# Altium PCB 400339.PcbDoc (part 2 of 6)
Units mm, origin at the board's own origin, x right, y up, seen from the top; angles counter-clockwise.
Board outline 146 x 63.5 mm, 4 copper layers (Top Layer, Mid-Layer 1, Mid-Layer 2, Bottom Layer), stack 1.505 mm thick; 400 components, 261 nets, 1523 pads, 1938 vias.
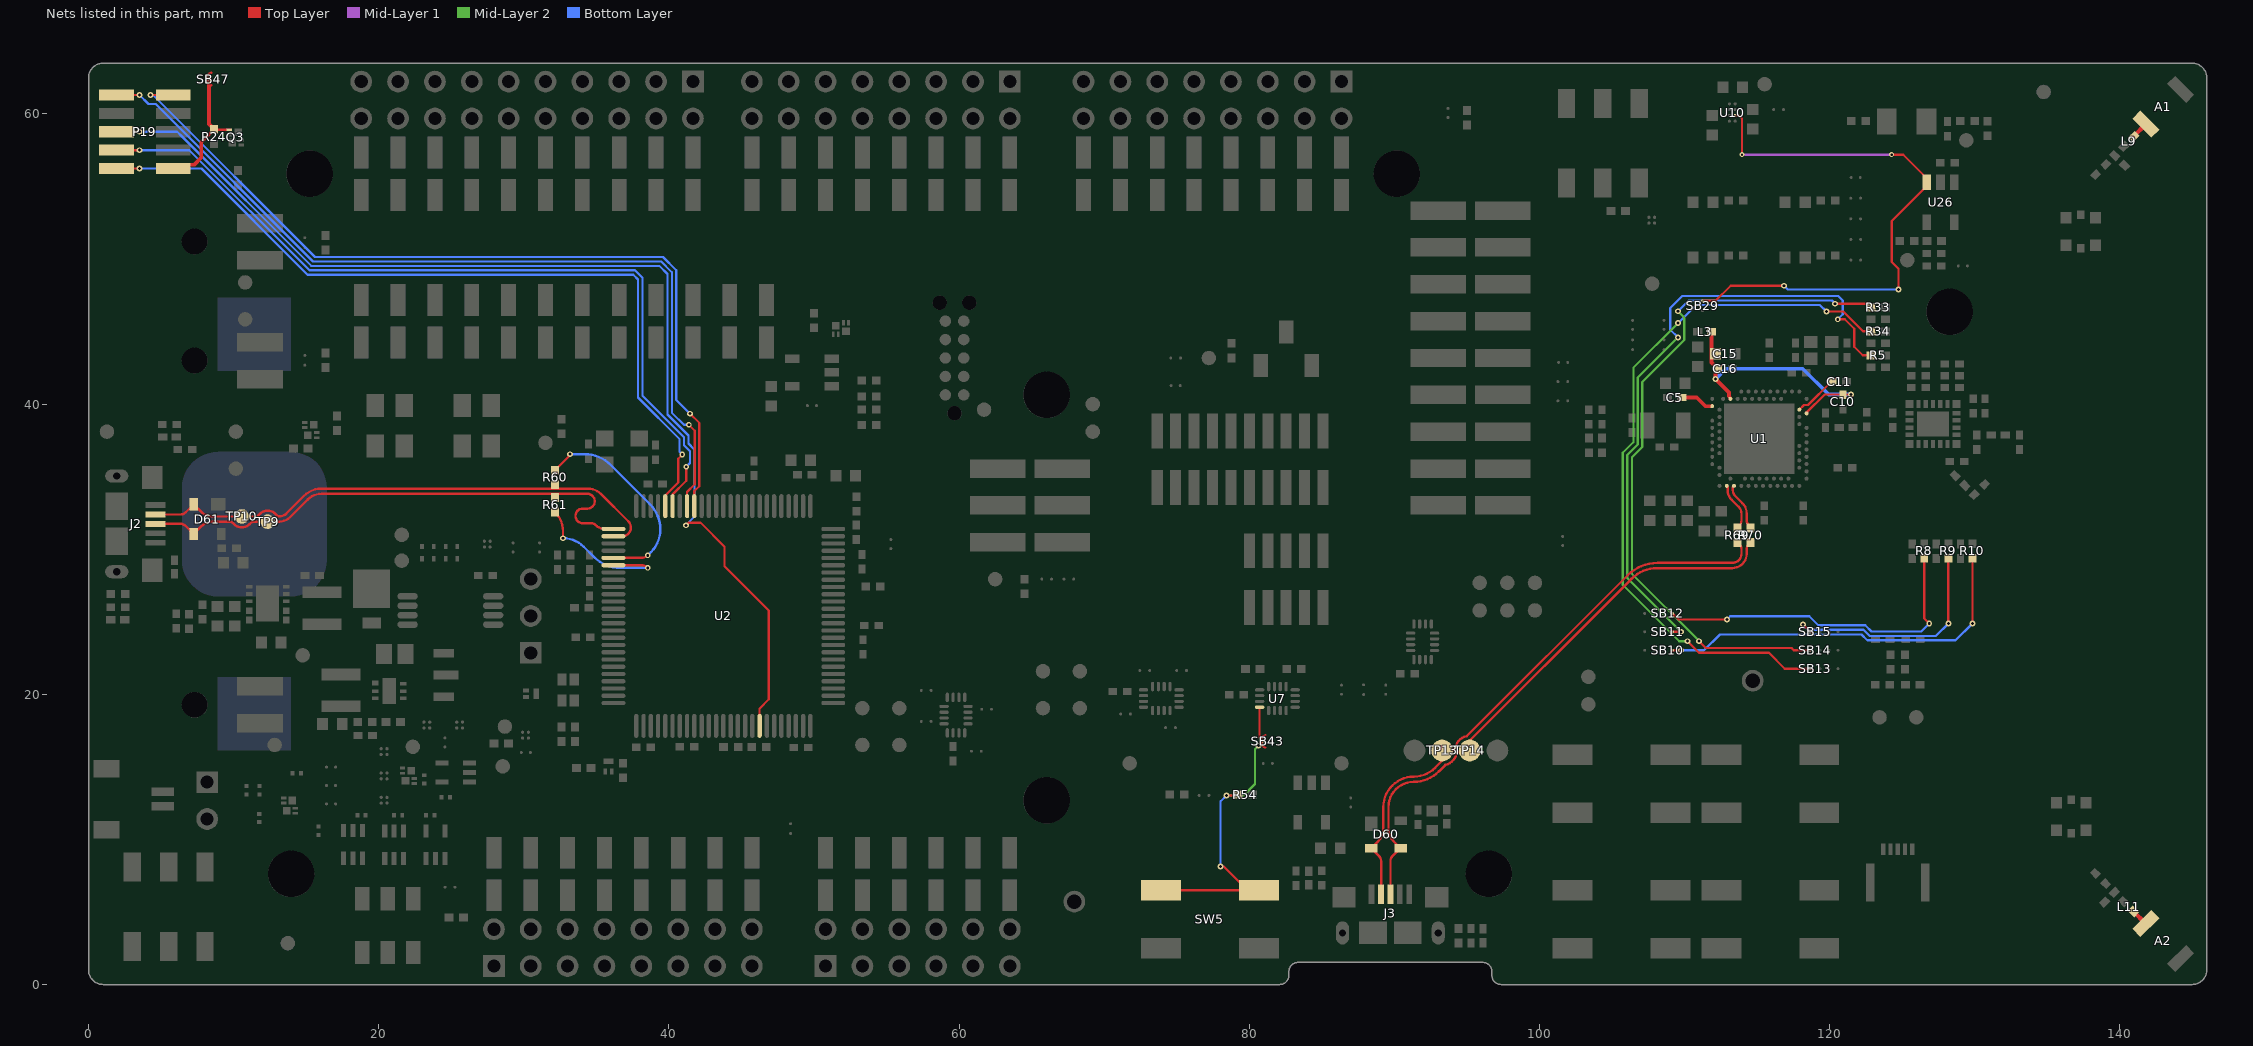
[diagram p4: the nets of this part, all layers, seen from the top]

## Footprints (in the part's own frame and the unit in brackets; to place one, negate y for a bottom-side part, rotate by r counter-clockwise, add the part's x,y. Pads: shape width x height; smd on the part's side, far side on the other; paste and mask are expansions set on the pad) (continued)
Solderbridge#4 [mm]
  round 0.2 smd paste-10: 1(-0.312,0) 2(0.312,0)
  Top Layer region: -0.077,-0.432 -0.152,-0.505 -0.271,-0.467 -0.335,-0.424 -0.409,-0.351 -0.462,-0.292 -0.521,-0.193 -0.549,-0.099 -0.544,0.122 -0.518,0.193 -0.434,0.33 -0.351,0.411 -0.259,0.469 -0.157,0.5 -0.107,0.483 -0.077,0.43
  Top Layer region: 0.077,0.432 0.152,0.505 0.271,0.467 0.335,0.424 0.409,0.351 0.462,0.292 0.521,0.193 0.549,0.099 0.544,-0.122 0.518,-0.193 0.434,-0.33 0.351,-0.411 0.259,-0.469 0.157,-0.5 0.107,-0.483 0.077,-0.43
  Top Layer lines w0.152: 0.153,0.431 cw(c0.042,0) 0.487,0 cw(c0.042,0) 0.312,-0.353 cw(c0.042,0) 0.153,-0.431 ; -0.153,0.431 ccw(c-0.042,0) -0.487,0 ccw(c-0.042,0) -0.153,-0.431
Solderbridge#5 [mm]
  round 0.2 smd paste-10: 1(-0.312,0) 2(0.312,0)
  Top Layer region: -0.077,-0.432 -0.152,-0.505 -0.271,-0.467 -0.335,-0.424 -0.409,-0.351 -0.462,-0.292 -0.521,-0.193 -0.549,-0.099 -0.544,0.122 -0.518,0.193 -0.434,0.33 -0.351,0.411 -0.259,0.469 -0.157,0.5 -0.107,0.483 -0.077,0.43
  Top Layer region: 0.077,0.432 0.152,0.505 0.271,0.467 0.335,0.424 0.409,0.351 0.462,0.292 0.521,0.193 0.549,0.099 0.544,-0.122 0.518,-0.193 0.434,-0.33 0.351,-0.411 0.259,-0.469 0.157,-0.5 0.107,-0.483 0.077,-0.43
  Top Layer lines w0.152: 0.153,0.431 cw(c0.042,0) 0.487,0 cw(c0.042,0) 0.153,-0.431 ; -0.153,0.431 ccw(c-0.042,0) -0.315,0.351 ccw(c-0.042,0) -0.482,0.066 ccw(c-0.042,0) -0.315,-0.351 ccw(c-0.042,0) -0.153,-0.431
Solderbridge_Shorted#1 [mm]
  round 0.2 smd paste-10: 1(-0.338,0) 2(0.338,0)
  Top Layer region: 0.102,0.432 0.178,0.505 0.296,0.467 0.361,0.424 0.434,0.351 0.488,0.292 0.546,0.193 0.574,0.099 0.569,-0.122 0.544,-0.193 0.46,-0.33 0.376,-0.411 0.284,-0.469 0.183,-0.5 0.132,-0.483 0.102,-0.43
  Top Layer region: -0.102,-0.432 -0.178,-0.505 -0.296,-0.467 -0.361,-0.424 -0.434,-0.351 -0.488,-0.292 -0.546,-0.193 -0.574,-0.099 -0.569,0.122 -0.544,0.193 -0.46,0.33 -0.376,0.411 -0.284,0.469 -0.183,0.5 -0.132,0.483 -0.102,0.43
  Top Layer lines w0.152: -0.178,0.431 ccw(c-0.068,0) -0.178,-0.431 ; 0.178,0.431 cw(c0.068,0) 0.178,-0.431
  Top Layer lines w0.203: -0.338,0 0.338,0
Solderbridge_Shorted#2 [mm]
  round 0.2 smd paste-10: 1(-0.338,0) 2(0.338,0)
  Top Layer region: 0.102,0.432 0.178,0.505 0.296,0.467 0.361,0.424 0.434,0.351 0.488,0.292 0.546,0.193 0.574,0.099 0.569,-0.122 0.544,-0.193 0.46,-0.33 0.376,-0.411 0.284,-0.469 0.183,-0.5 0.132,-0.483 0.102,-0.43
  Top Layer region: -0.102,-0.432 -0.178,-0.505 -0.296,-0.467 -0.361,-0.424 -0.434,-0.351 -0.488,-0.292 -0.546,-0.193 -0.574,-0.099 -0.569,0.122 -0.544,0.193 -0.46,0.33 -0.376,0.411 -0.284,0.469 -0.183,0.5 -0.132,0.483 -0.102,0.43
  Top Layer lines w0.152: -0.178,-0.431 cw(c-0.068,0) -0.512,0 cw(c-0.068,0) -0.178,0.431 ; 0.178,-0.431 ccw(c0.068,0) 0.178,0.431
  Top Layer lines w0.203: -0.338,0 0.338,0
SOT65P210X100-5N [mm] "SOT23, 5-Leads, Body 2,2x2,4mm (max), Pitch 0,65mm, IPC Medium Density"
  rect 0.9x0.35 smd: 1(-0.95,0.65) 2(-0.95,0) 3(-0.95,-0.65) 4(0.95,-0.65) 5(0.95,0.65)
  silkscreen extent -1.08,-1.1 0.1,1.5, body extent -1.1,-1 1.1,1, height 0.97
SOT65P210X100-6N [mm] "SOT23, 6-Leads, Body 2,2x2,4mm (max), Pitch 0,65mm, IPC Medium Density"
  rect 0.9x0.35 smd: 1(-0.95,0.65) 2(-0.95,0) 3(-0.95,-0.65) 4(0.95,-0.65) 5(0.95,0) 6(0.95,0.65)
  silkscreen extent -1.41,-1.1 0.1,1.34, body extent -1.05,-1 1.05,1, height 0.92
SOT89-150P409X160-3N [mm] "SOT89, 3-Leads, Body 4.50x2.45mm, Pitch 1.50mm, Lead Span 4.1mm, IPC Medium Density"
  rect 1.4x0.6 smd: 1(-1.8,1.5) 3(-1.8,-1.5)
  rect 1.7x0.6 smd: 2(-1.65,0)
  Top Layer region: -0.8,0.3 -0.15,0.95 1.85,0.95 2.5,0.3 2.5,-0.3 1.85,-0.95 -0.15,-0.95 -0.8,-0.3
  silkscreen extent -2.05,-2.3 1.32,2.47, body extent -2.2,-2.3 1.93,2.3, height 1.6
SOT95P280X140-5N [mm] "SOT23, 5-Leads, Body 2,90x2,80mm, Pitch 0,95mm, IPC Medium Density"
  rect 1x0.6 smd: 1(-1.35,0.95) 2(-1.35,0) 3(-1.35,-0.95) 4(1.35,-0.95) 5(1.35,0.95)
  silkscreen extent -1.47,-1.5 0.45,1.93, body extent -1.5,-1.55 1.5,1.55, height 1.4
SOT95P282X145-5N [mm] "SOT23, 5-Leads, Body 2.96x2.82mm, Pitch 0.95mm, IPC Medium Density"
  rect 1.05x0.6 smd: 1(-1.375,0.95) 2(-1.375,0) 3(-1.375,-0.95) 4(1.375,-0.95) 5(1.375,0.95)
  silkscreen extent -1.5,-1.55 0.45,1.93, body extent -1.5,-1.55 1.5,1.55, height 1.45
SOT190P230X110-4L [mm] "SOT143, 4-Leads, Body 3.0x2.5mm (max), Pitch 1.90mm, IPC High Density"
  rect 0.85x1 smd: 1(-1.025,0.75)
  rect 0.85x0.6 smd: 2(-1.025,-0.95) 3(1.025,-0.95) 4(1.025,0.95)
  silkscreen extent -1.15,-1.5 0.7,1.92, body extent -1.21,-1.46 1.21,1.46, height 1
Switch-PB-6.2x6.3mm-SMD [mm] "6.2×6.5mm TACT Switch, without ground connector"
  rect 2.75x1.4 smd: 1(-3.375,2) 1(3.375,2) 2(-3.375,-2) 2(3.375,-2)
  silkscreen extent -3,-3 3,3, body extent -4,-3 4,3.3, height 3.1
Switch-Slide-J-Lead-DP3T-13x3.5mm [mm] "Slide Switch - DP3T, SMD, ON-ON-ON"
  rect 1.2x1.6 smd: 1(-4,-1.4) 2(-2,-1.4) 3(2,-1.4) 4(4,-1.4) 5(-4,1.4) 6(-2,1.4) 7(2,1.4) 8(4,1.4)
  silkscreen extent -6,-1.75 6,1.75, body extent -6,-1.8 6,1.7, height 5.5
TC2050-IDC-NLFP [mil]
  round 39 hole 39 unplated: 0(-150,0) 0(150,-40) 0(150,40)
  round 31 smd paste-196.85: 1(-100,-25) 2(-50,-25) 3(0,-25) 4(50,-25) 5(100,-25) 6(100,25) 7(50,25) 8(0,25) 9(-50,25) 10(-100,25)
  Top Layer pour cut-out: -100,25 -100,-25 100,-25 100,25
TESTPAD-TH [mm]
  round 1.5 hole 1: 1(0,0)
  silkscreen extent -1,-1 1,1
TP_SMD_Ø1.0mm [mm]
  round 1 smd paste-5: 1(0,0)
  silkscreen extent -0.7,-0.7 0.7,0.7
TP_SMD_Ø1.5mm [mm]
  round 1.5 smd paste-5: 1(0,0)
  silkscreen extent -0.95,-0.95 0.95,0.95
TSOP65P640X120-8N [mm] "TSOP, 8-Leads, Body 3.00x4.40mm, Pitch 0.65mm, IPC Medium Density"
  oval 1.4x0.45 smd: 1(-2.95,0.975) 2(-2.95,0.325) 3(-2.95,-0.325) 4(-2.95,-0.975) 5(2.95,-0.975) 6(2.95,-0.325) 7(2.95,0.325) 8(2.95,0.975)
  silkscreen extent -3.07,-1.55 1.85,1.87, body extent -3.2,-1.55 3.2,1.55, height 1.2
TSQFP50P1600X1600X160-100N [mm] "TSQFP, 100-Leads, Body 16,0x16,0mm (max), Pitch 0,50mm, IPC Medium Density"
  oval 1.65x0.3 smd: 1(-7.575,6) 2(-7.575,5.5) 3(-7.575,5) 4(-7.575,4.5) 5(-7.575,4) 6(-7.575,3.5) 7(-7.575,3) 8(-7.575,2.5) 9(-7.575,2) 10(-7.575,1.5) 11(-7.575,1) 12(-7.575,0.5) 13(-7.575,0) 14(-7.575,-0.5) 15(-7.575,-1) 16(-7.575,-1.5) 17(-7.575,-2) 18(-7.575,-2.5) 19(-7.575,-3) 20(-7.575,-3.5) 21(-7.575,-4) 22(-7.575,-4.5) 23(-7.575,-5) 24(-7.575,-5.5) 25(-7.575,-6) 51(7.575,-6) 52(7.575,-5.5) 53(7.575,-5) 54(7.575,-4.5) 55(7.575,-4) 56(7.575,-3.5) 57(7.575,-3) 58(7.575,-2.5) 59(7.575,-2) 60(7.575,-1.5) 61(7.575,-1) 62(7.575,-0.5) 63(7.575,0) 64(7.575,0.5) 65(7.575,1) 66(7.575,1.5) 67(7.575,2) 68(7.575,2.5) 69(7.575,3) 70(7.575,3.5) 71(7.575,4) 72(7.575,4.5) 73(7.575,5) 74(7.575,5.5) 75(7.575,6)
  oval 0.3x1.65 smd: 26(-6,-7.575) 27(-5.5,-7.575) 28(-5,-7.575) 29(-4.5,-7.575) 30(-4,-7.575) 31(-3.5,-7.575) 32(-3,-7.575) 33(-2.5,-7.575) 34(-2,-7.575) 35(-1.5,-7.575) 36(-1,-7.575) 37(-0.5,-7.575) 38(0,-7.575) 39(0.5,-7.575) 40(1,-7.575) 41(1.5,-7.575) 42(2,-7.575) 43(2.5,-7.575) 44(3,-7.575) 45(3.5,-7.575) 46(4,-7.575) 47(4.5,-7.575) 48(5,-7.575) 49(5.5,-7.575) 50(6,-7.575) 76(6,7.575) 77(5.5,7.575) 78(5,7.575) 79(4.5,7.575) 80(4,7.575) 81(3.5,7.575) 82(3,7.575) 83(2.5,7.575) 84(2,7.575) 85(1.5,7.575) 86(1,7.575) 87(0.5,7.575) 88(0,7.575) 89(-0.5,7.575) 90(-1,7.575) 91(-1.5,7.575) 92(-2,7.575) 93(-2.5,7.575) 94(-3,7.575) 95(-3.5,7.575) 96(-4,7.575) 97(-4.5,7.575) 98(-5,7.575) 99(-5.5,7.575) 100(-6,7.575)
  silkscreen extent -7.7,-6.35 6.35,6.82, body extent -8,-8 8,8, height 1.6
TY-NR3015 [mm] "Molded Inductor, 2-Leads, Body 3.00x3.00mm, IPC Medium Density"
  rect 0.8x2.7 smd: 1(-1.1,0) 2(1.1,0)
  silkscreen extent -2.05,-1.55 1.55,1.75, body extent -1.5,-1.5 1.5,1.5, height 1.35
USB-Micro-B-RA-SMD-PiP [mm] "Micro USB B SMT"
  rect 1.35x0.4 smd: 1(0,1.3) 2(0,0.65) 3(0,0) 4(0,-0.65) 5(0,-1.3)
  oval 1.6x0.9 hole 0.5 slot 1.2 at 0 deg: 6(-2.675,-3.3) 6(-2.675,3.3)
  oval 2x1.5 on Top Paste: 6(-2.675,-3.3) 6(-2.675,3.3)
  rect 1.55x1.9 smd: 6(-2.675,-1.2) 6(-2.675,1.2)
  rect 1.4x1.6 smd: 6(-0.225,-3.2) 6(-0.225,3.2)
  silkscreen extent -4.75,-3.75 0.25,3.75, body extent -5.28,-4.1 0.15,4.1, height 2.72
USP-6C [mm] "DFN, 6-Leads, Body 2.00x1.80mm, Pitch 0.50mm, Thermal Pad 1.00x1.40mm, IPC Medium Density"
  rect 0.45x0.35 smd paste-0.05: 1(-0.975,0.55)
  rect 0.45x0.25 smd paste-0.05: 2(-0.975,0) 3(-0.975,-0.5) 4(0.975,-0.5) 5(0.975,0) 6(0.975,0.5)
  rect 0.9x1.8 smd paste-2: 7(0,0)
  Top Layer region: -0.5,-0.8 0.5,-0.8 0.5,0.8 -0.5,0.8
  silkscreen extent -1.42,-1.07 0.97,1.12, body extent -0.93,-1.02 0.93,1.02, height 0.6
X2DFN35P100X130X35-6N [mm] "X2-DFN, 6-Leads, Body 1.00x1.30mm, Pitch 0.35mm, IPC Medium Density"
  rect 0.375x0.2 smd mask+0.06: 1(-0.407,0.53) 2(-0.407,0.18) 4(0.408,-0.53) 5(0.408,-0.18)
  rect 0.52x0.52 smd mask+0.06: 3(-0.2,-0.35) 6(0.2,0.35)
  silkscreen extent -0.87,-0.71 0.59,1, body extent -0.53,-0.65 0.53,0.65, height 0.35
XQFN40P180X260X50-16N [mm] "QFN, 16-Leads, Body 1.80x2.60mm, Pitch 0.40mm, IPC Medium Density"
  oval 0.65x0.22 smd paste-0.02 mask+0.062: 1(-0.825,0.6) 2(-0.825,0.2) 3(-0.825,-0.2) 4(-0.825,-0.6) 9(0.825,-0.6) 10(0.825,-0.2) 11(0.825,0.2) 12(0.825,0.6)
  oval 0.22x0.65 smd paste-0.02 mask+0.062: 5(-0.6,-1.225) 6(-0.2,-1.225) 7(0.2,-1.225) 8(0.6,-1.225) 13(0.6,1.225) 14(0.2,1.225) 15(-0.2,1.225) 16(-0.6,1.225)
  silkscreen extent -1.45,-1.4 1,1.4, body extent -0.91,-1.31 0.91,1.31, height 0.55
XTAL_3215 [mm] "XTAL SMD 3.2 x 1.5 mm"
  rect 1x1.8 smd: 1(-1.25,0) 2(1.25,0)
  silkscreen extent -0.6,-0.75 0.6,0.75, body extent -1.6,-0.75 1.6,0.75, height 0.81

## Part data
A1 A2: library part "Johanson 2450AT18B100", "2.45 GHz chip antenna", Manufacturer="Johanson Technology", Part number IPS=00000007781, Supplier Part Number 1=712-1006-1-ND
Bat1: library part "Bat Holder CR2032 SMD", "Bat Holder CR2032 SMD", Manufacturer=Comfortable, Manufacturer Part Number=BC-2001, Part number IPS=N.A., Supplier Part Number 1="BC-2001/T & R"
C1 C2 C17 C18: library part C0402-12p, "Capacitor, NP0, ±2%", Part number IPS=00000002398
C3 C4 C49 C72 C73 C75 C76 C101: library part C0402-1.0p, "Capacitor, NP0, ±0.1pF", Part number IPS=N.A., Supplier Part Number 1=490-6073-1-ND
C5 C7 C8 C12 C24 C25 C26 C28 C31 C32 C33 C34 C35 C36 C37 C40 C41 C42 C43 C45 C48 C50 C53 C57 C62 C65 C66 C67 C68 C69 C71 C85: library part C0402-100n, "Capacitor, X7R, ±10%", Part number IPS=00000005296
C6 C20: library part C0603-4µ7-6.3V-X7R, "Capacitor, X7R, ±10%", Manufacturer=Samsung, Manufacturer Part Number=CL10B475KQ8NQNC, Part number IPS=N.A., Supplier Part Number 1=1276-2087-1-ND
C9: library part C0402-820p, "Capacitor, NP0, ±5%", Part number IPS=N.A.
C10 C13 C22 C51 C52: library part C0402-N.C., "Not mounted", Part number IPS=N.A.
C11: library part C0402-100p, "Capacitor, NP0, ±5%", Part number IPS=00000002361
C14 C15 C91 C92: library part C0603-1µ0, "Capacitor, X7R, ±10%", Part number IPS=00000000616
C16: library part C0402-47n, "Capacitor, X7R, ±10%", Part number IPS=N.A.
C19 C21: library part C0603-4µ7-10V-X7S, "Capacitor, X7S, ±10%", Part number IPS=N.A., Supplier Part Number 1=445-14258-1-ND
C23 C58 C99: library part C0402-4µ7, "Capacitor, X5R, ±20%", Part number IPS=00000001251, Supplier Part Number 1=490-13252-1-ND
C27: library part C0402-10p, "Capacitor, NP0, ±2%", Part number IPS=N.A., Supplier Part Number 1=712-1252-1-ND
C29 C30: library part C0402-18p, "Capacitor, NP0, ±5%", Part number IPS=N.A.
C38 C39 C61 C64 C95 C96: library part C0603-10µ, "Capacitor, X5R, ±20%", Part number IPS=00000007785
C44 C60 C63 C94: library part C0402-10n, "Capacitor, X7R, ±10%", Part number IPS=00000007784
C46 C47: library part C0402-300p, "Capacitor, NP0, ±5%", Part number IPS=N.A., Supplier Part Number 1=490-3234-1-ND
C54 C55 C56 C59 C70 C74 C77 C78 C79: library part C0402-1n0, "Capacitor, X7R, ±10%", Part number IPS=N.A.
C80 C82 C83 C88: library part C0603-10µF-25V, "Capacitor, 0603, 25V, X5R", Part number IPS=N.A.
C81: library part C0402-15p, "Capacitor, NP0, ±5%", Part number IPS=00000002401
C84: library part C0402-470n, "Capacitor, X5R, ±10%", Part number IPS=N.A.
C86: library part C0805-4µ7, "Capacitor, X5R, ±10%", Part number IPS=N.A.
C87: library part C0402-150p, "Capacitor, NP0, ±5%", Part number IPS=00000007972
C89 C90 C93 C103: library part C0201-100n, "Capacitor, X5R, ±10%", Part number IPS=00000001248
C97: library part C0402-1µ0, "Capacitor, X5R, ±5%", Part number IPS=00000007786, Supplier Part Number 1=1276-1444-1-ND
C98: library part C0402-TBD, "Chip Cap 0402", Part number IPS=N.A.
D60 D61: "Ultra low capacitance double rail-to-rail ESD protection diode", Manufacturer=NXP, Part number IPS=00000009951, Supplier Part Number 1=568-4140-1-ND
D80 D81 D82 D83: "20V schottky barrier diode, Vf 350 mV @ 100 mA, Ir 2.0 µA @ 10 V, If 500 mA", Manufacturer="ON Semiconductor", Part number IPS=N.A., Supplier Part Number 1=NSR0620P2T5GOSCT-ND
D84: "Diode Schottky Vf=0.455V @ 100mA, Vr=10V, If=1000mA, Ir=1µA @ 10V", Manufacturer="ON Semiconductor", Manufacturer Part Number=MBRM110ET1G, Part number IPS=N.A., Supplier Part Number 1=MBRM110ET1GOSTR-ND
FB60 FB61 FB62 FB63 FB64 FB65: library part FB0402-120R@100M-500mA, "Ferrite Bead, 120 Ohm @ 100MHz, 500mA, 250 mOhm Max", Manufacturer=Murata, Manufacturer Part Number=BLM15AG121SN1D, Part number IPS=N.A., Supplier Part Number 1=490-1005-1-ND
Fid1 Fid2: library part Fid-Mark, "Fiducial Mark", Part number IPS=N.A.
J1 J7: "Coaxial Connector with Switch", Manufacturer=Murata, Part number IPS=N.A., Supplier Part Number 1=490-4981-1-ND
J2 J3: library part USB-Micro-B-RA-SMD-PiP, "MicroUSB-B-SMT", Manufacturer="Allen Creations Corp.", Manufacturer Part Number=AJU55-BS2111-L, Part number IPS=00000007790
J4: library part TC2050-IDC-NLFP, "CBL PLUG-OF-NAILS 10-PIN", Manufacturer="Tag-Connect LLC", Part number IPS=N.A., Supplier Part Number 1=TC2050-IDC-NL-ND
J5: library part FPC_05P-0.5mm-RA-SMD, "0.5mm FPC, 5P,Right Angle SMT,Double Contact,H=1.2mm,White, Tin plated", Manufacturer=W-CON, Manufacturer Part Number=5141-05RZDNWR01, Part number IPS=00000007792
J6: library part SM02B-SRSS-TB, "1.0mm pitch connector side entry SMD", Manufacturer=JST, Manufacturer Part Number=SM02B-SRSS-TB(LF)(SN), Part number IPS=00000007791, Supplier Part Number 1=455-1802-1-ND
L1: library part L0402-3n9, "Inductor, 170mA, ±0.1nH", Manufacturer=Murata, Manufacturer Part Number=LQP15MN3N9B02D, Part number IPS=00000007793, Supplier Part Number 1=490-1131-1-ND
L2 L4: library part L0603-10µ, "Inductor, 80mA, ±10%", Manufacturer="Taiyo Yuden", Manufacturer Part Number=LBMF1608T100K, Part number IPS=00000007794, Supplier Part Number 1=587-1714-1-ND
L3: library part L0402-15n, "Inductor, 320mA, ±5%", Manufacturer="Taiyo Yuden", Manufacturer Part Number=HK100515NJ-T, Part number IPS=00000001262, Supplier Part Number 1=587-1521-1-ND
L5: library part L0603-1µH, "FIXED IND 1UH 1A 200 MOHM SMD", Manufacturer="Abracon Corporation", Manufacturer Part Number=ASMPH-0603-1R0M-T, Part number IPS=N:A, Supplier Part Number 1=535-12263-2-ND
L6 L7: library part L0402-2n7-HT, "THIN FILM 2.7NH ±0.1nH 0402", Manufacturer="Wurth Elektronik", Manufacturer Part Number=744901027, Part number IPS=N.A., Supplier Part Number 1=732-2917-1-ND
L8 L10: library part L0402-3n0, "FIXED IND 3NH 800MA 200 MOHM SMD", Manufacturer="TDK Corporation", Manufacturer Part Number=MLG1005S3N0BT000, Part number IPS=N.A., Supplier Part Number 1=445-16293-1-ND
L9 L11: library part L0402-3n3-HT, "THIN FILM 3.3NH ±0.1nH 0402", Manufacturer="Wurth Elektronik", Manufacturer Part Number=744901033, Part number IPS=N.A., Supplier Part Number 1=732-2918-1-ND
L80: library part NR3015-2µ2-1.5A-72mOhm, "Ferrite Inductor, Shielded, 1,5A, 72mOhm", Manufacturer="Taiyo Yuden", Manufacturer Part Number=NR3015T2R2M, Part number IPS=N.A., Supplier Part Number 1=587-1648-1-ND
L81: library part NR3015-4µ7-1.04A-144mOhm, "Ferrite Inductor, Shielded, 1,04A, 144mOhm", Manufacturer="Taiyo Yuden", Manufacturer Part Number=NR3015T4R7M, Part number IPS=N.A., Supplier Part Number 1=587-1649-1-ND
LED1 LED2 LED3 LED4: library part "VS 25C7M5", "LED, Green, 0603, 573nm, Vf=2.0V, 24mcd, - 40 to +85°C", Manufacturer="Victory Electronics", Part number IPS=N.A.
LED5: library part LTST-C195KGJRKT, "Ultra bright AlInGaP Bi-Color LED", Manufacturer="Lite-On Inc", Part number IPS=N.A., Supplier Part Number 1=160-1452-1-ND
P1 P3 P6: library part "Socket 1x8 SMD", "Socket 1x8, 2.54mm (100mil), SMD", Manufacturer=W-CON, Manufacturer Part Number=2171-108MS0CUNR1, Part number IPS=N.A.
P2: library part "Socket 1x6 SMD", "Socket 1x6, 2.54mm (100mil), SMD", Manufacturer=W-CON, Manufacturer Part Number=2171-106MS0CUNR1, Part number IPS=N.A.
P4: library part "Socket 1x10 SMD", "Socket 1x10, 2.54mm (100mil), SMD", Manufacturer=W-CON, Manufacturer Part Number=2171-110MS0CUNR1, Part number IPS=N.A.
P5: library part "Pin Header 2x3 SMD", "Pin Header 2x3, 2.54mm (100mil) SMD", Manufacturer=W-CON, Manufacturer Part Number=1125-1203S0M116R1, Part number IPS=N.A.
P7 P9 P12: library part "Pin List 1x8 SMD, N.C.", "Pin List 1x8, 2.54mm (100mil), SMD", Manufacturer=W-CON, Manufacturer Part Number=1125-1108S0M116R2, Part number IPS=N.A.
P8: library part "Pin List 1x6 SMD, N.C.", "Pin List 1x6, 2.54mm (100mil), SMD", Manufacturer=W-CON, Manufacturer Part Number=1125-1106S0M116R2, Part number IPS=N.A.
P10: library part "Pin List 1x10 SMD, N.C.", "Pin List 1x10, 2.54mm (100mil), SMD", Manufacturer=W-CON, Manufacturer Part Number=1125-1110S0M116R2, Part number IPS=N.A.
P11: library part "Socket 2x3 SMD Bottom, N.C.", "Socket 2x3, 2.54mm (100mil), SMD", Manufacturer=W-CON, Manufacturer Part Number=2171-203MS0CUNR1, Part number IPS=N.A.
P13 P15 P17: library part "Pin Header 2x8, N.C.", "Pin Header 2x8, 2.54mm (100mil)", Part number IPS=N.A.
P14: library part "Pin Header 2x6, N.C.", "Pin Header 2x6, 2.54mm (100mil)", Part number IPS=N.A.
P16: library part "Pin Header 2x10, N.C.", "Pin Header 2x10, 2.54mm (100mil)", Part number IPS=N.A.
P18 P19: library part "Pin Header 2x5 SMD, 1.27mm, KS", "Pin Header 2x5, 1.27mm (50mil), SMD, Keying Shroud", Manufacturer=W-CON, Manufacturer Part Number=3132-10MS0BK00R1, Part number IPS=N.A.
P20: library part "Pin List 1x12 SMD", "Pin List 1x12, 2.54mm (100mil), SMD", Manufacturer=W-CON, Manufacturer Part Number=1125-1112S0M116R2, Part number IPS=N.A.
P21 P22 P23: library part "Pin List Ang 1x2 SMD, 2.54mm", "Pin List 1x2, 2.54mm (100mil), Right Angled, SMD", Manufacturer=W-CON, Manufacturer Part Number=1125B-1102S0Z135R2, Part number IPS=N.A.
P24: library part "Socket 2x9 SMD", "Socket 2x9, 2.54mm (100mil), SMD", Manufacturer=W-CON, Manufacturer Part Number=2171-209MS0CUNR1, Part number IPS=N.A.
P25: library part "Pin Header 2x10 SMD, 1.27mm, KS, N.C.", "Pin Header 2x10, 1.27mm (50mil), SMD, Keying Shroud", Manufacturer=W-CON, Manufacturer Part Number=3132-20MS0BK00R1, Part number IPS=N.A.
P26: library part "Socket 1x12 SMD, N.C.", "Socket 1x12, 2.54mm (100mil), SMD", Manufacturer=W-CON, Manufacturer Part Number=2171-112MS0CUNR1, Part number IPS=N.A.
P27: library part "Pin List 1x2, N.C.", "Pin List 1x2, 2.54mm (100mil)", Part number IPS=N.A.
P28: library part "Pin List 1x3, N.C.", "Pin List 1x3, 2.54mm (100mil)", Part number IPS=N.A.
Q1 Q2 Q3 Q4: "MOSFET N/P-CHA 30V 1.1A DFN1310", Manufacturer="Diodes Incorporated", Part number IPS=N.A., Supplier Part Number 1=DMC3730UFL3-7DICT-ND
Q5: "Dual N-Channel FET", Manufacturer="Diodes Incorporated", Part number IPS=N.A., Supplier Part Number 1=DMN1150UFL3-7DICT-ND
Q80: "45V NPN high gain power transistor", Manufacturer="Diodes Incorporated", Part number IPS=N.A., Supplier Part Number 1=FCX690BCT-ND
Q82 Q83: "N-Channel MOSFET, 20V, 1A, 470mOhm, 400mW", Manufacturer="Rohm Semiconductor", Part number IPS=N.A., Supplier Part Number 1=RV2C010UNT2LCT-ND
R1 R2 R30 R44 R46 R69 R70: library part R0402-0R, "Resistor, ±5%, 0.063W", Part number IPS=N.A., Supplier Part Number 1=146-9661
R3 R4 R22 R23 R24 R27 R49 R62 R63: library part R0402-10k, "Resistor, ±1%, 0.063W", Part number IPS=00000002093, Supplier Part Number 1=173-8864
R5 R8 R9 R10 R33 R34 R93: library part R0402-1k0, "Resistor, ±1%, 0.063W", Part number IPS=00000002218, Supplier Part Number 1=173-8850
R6 R86 R89: library part R0201-1M0, "Resistor, ±1%, 0.05W", Part number IPS=N.A.
R11 R13 R16: library part R0402-39k, "Resistor, ±1%, 0.063W", Part number IPS=N.A., Supplier Part Number 1=173-8871
R12: library part R1206-0R, "RES SMD 0R 1% 1206", Part number IPS=N.A.
R14: library part R0402-TBD, "Chip Res 0402", Part number IPS=N.A.
R15: library part R0402-100k, "Resistor, ±1%, 0.063W", Part number IPS=00000003667, Supplier Part Number 1=173-8877
R18: library part R0201-100k, "Resistor, ±1%, 0.05W", Part number IPS=N.A.
R20 R21 R47 R48 R50 R51: library part R0402-220, "Resistor, ±1%, 0.063W", Part number IPS=N.A., Supplier Part Number 1=173-8841
R25: library part R0402-6k8, "Resistor, ±1%, 0.063W", Part number IPS=N.A., Supplier Part Number 1=173-8862
R26: library part R0402-47k, "Resistor, ±1%, 0.063W", Part number IPS=N.A., Supplier Part Number 1=146-9719
R28 R29: library part R0402-150, "Resistor, ±1%, 0.063W", Part number IPS=N.A., Supplier Part Number 1=173-8839
R40: library part R0402-150k, "Resistor, ±1%, 0.063W", Part number IPS=N.A., Supplier Part Number 1=165-2753
R41 R68 R87: library part R0402-1M0, "Resistor, ±1%, 0.063W", Part number IPS=00000006807
R43 R45 R54 R88 R90 R91: library part R0402-N.C., "Not mounted", Part number IPS=N.A.
R52 R53 R64 R65 R66 R67: library part R0402-4k7, "Resistor, ±1%, 0.063W", Part number IPS=00000003433, Supplier Part Number 1=173-8858
R60 R61: library part R0402-39R, "Resistor, ±1%, 0.063W", Part number IPS=00000000821, Supplier Part Number 1=173-8831
R80: library part R0402-270k, "Resistor, ±1%, 0.063W", Part number IPS=N.A.
R81: library part R0402-30k, "Resistor, ±1%, 0.063W", Part number IPS=N.A.
R82: library part R0402-330k, "Resistor, ±1%, 0.063W", Part number IPS=N.A.
R83: library part R0201-820k, "Resistor, ±1%, 0.05W", Part number IPS=N.A.
R84: library part R0402-120k, "Resistor, ±1%, 0.063W", Part number IPS=N.A., Supplier Part Number 1=169-2508
R85: library part R0201-470k, "Resistor, ±1%, 0.05W", Part number IPS=N.A.
R92 R94: library part R0402-10M, "Resistor, ±1%, 0.063W", Part number IPS=N.A.
SB1 SB2 SB5 SB6 SB7 SB8 SB10 SB11 SB12 SB13 SB14 SB15 SB16 SB26 SB28 SB29 SB32 SB33 SB38 SB40 SB41 SB42 SB50 SB51 SB52 SB53 SB54 SB55 SB56 SB57 SB58 SB60 SB65: library part "Solderbridge Shorted", "Shorted Solderbridge", Part number IPS=N.A.
SB3 SB4 SB9 SB17 SB20 SB21 SB22 SB23 SB24 SB25 SB27 SB30 SB31 SB34 SB35 SB36 SB37 SB39 SB43 SB44 SB45 SB46 SB47 SB48 SB49 SB59 SB61 SB80 SB81: Part number IPS=N.A.
SW1 SW2 SW3 SW4 SW5: library part Switch-PB-6.2x6.3mm-SMD, "Tactile Switch, SPNO, SMD, 160gf, 6.2x6.3x2.5mm", Manufacturer=Dailywell, Manufacturer Part Number=TS604VM1-025BR-R, Part number IPS=00000007812
SW6 SW8: "Slide Switch DPDT", Manufacturer=Dailywell, Part number IPS=N.A.
SW7: library part CJS-1200TA, "SMD slide Switch (ON-ON)", Manufacturer="Copal Electronics Inc", Part number IPS=N.A., Supplier Part Number 1=563-1021-2-ND
SW9: "Slide Switch DP3T 300mA 6V", Manufacturer="C&K Components", Part number IPS=N.A., Supplier Part Number 1=CKN10725CT-ND
SW10: "Slide Switch DPDT J Hook", Manufacturer="Copal Electronics Inc", Part number IPS=N.A., Supplier Part Number 1=CAS220JTR-ND
TP1 TP2 TP3 TP4 TP5 TP6 TP7 TP8 TP9 TP10 TP11 TP12 TP17 TP18 TP19 TP20 TP21 TP22 TP23 TP24 TP25 TP26 TP27 TP28 TP29 TP30 TP31 TP32 TP33 TP34 TP35 TP36 TP37 TP38 TP39 TP42 TP43 TP44 TP45 TP46 TP47 TP48 TP49 TP50: library part TP_SMD_Ø1.0MM, "1.0mm circular SMD testpad", Manufacturer="Nordic Semiconductor", Part number IPS=N.A.
TP13 TP14 TP15 TP16: library part TP_SMD_Ø1.5MM, "1.0mm circular SMD testpad", Manufacturer="Nordic Semiconductor", Part number IPS=N.A.
TP40 TP41: library part "Testpoint TH", "Testpoint, through hole", Part number IPS=N.A.
U1: library part nRF52840-QIAAC0, "Multi-protocol Bluetooth Low Energy, IEEE 802.15.4, ANT and 2.4GHz proprietary system-on-chip", Manufacturer="Nordic Semiconductor", Part number IPS=N.A.
U2: "IC MCU 32bit 128kB flash 100LQFP", Manufacturer=Atmel, Part number IPS=N.A., Supplier Part Number 1=ATSAM3U2CA-AU-ND
U3 U21: library part 74LVC1G11GW, "Single 3-input AND gate", Manufacturer="NXP Semiconductors", Part number IPS=N.A., Supplier Part Number 1=568-7757-1-ND
U4 U13 U14 U15 U16 U17 U18 U24: "Semtech, 2A Low Vin, Very Low Ron, Load Switch, 4DSBGA", Manufacturer="Semtech Corporation", Part number IPS=N.A., Supplier Part Number 1=SC728CSTRTCT-ND
U5 U6 U7 U8: "Data / Audio Low-Voltage Dual DPDT Analog Switch", Manufacturer="Fairchild Semiconductor", Part number IPS=N.A., Supplier Part Number 1=FSA2466UMXCT-ND
U9: "2.4 GHz ZigBee®/Thread/Bluetooth® Smart Front-End Module", Manufacturer=Skyworks, Part number IPS=N.A.
U10: library part ISL9123IINZ, "Ultra-Low IQ Buck Regulator with Bypass", Manufacturer=Intersil, Part number IPS=N.A.
U11: library part XC9236D08CER-G, "600mA Driver Transistor Built-In, Synchronous Step-Down DC/DC Converters", Manufacturer="Torex Semiconductor", Part number IPS=N.A., Supplier Part Number 1=865-XC9236D08CER-G
U12: library part XC9131H05CDR-G, "1A Driver Transistor Built-In, Multi Functional Step-Up DC/DC Converter", Manufacturer="Torex Semiconductor", Part number IPS=N.A., Supplier Part Number 1=XC9131H05CDR-G-ND
U19: "Precision very low power CMOS dual operational amplifier", Manufacturer=STMicroelectronics, Part number IPS=N.A., Supplier Part Number 1=497-8085-1-ND
U20 U25: library part 74LVC1G08GW, "Single 2-Input AND Gate", Manufacturer="NXP Semiconductors", Part number IPS=N.A., Supplier Part Number 1=568-1580-1-ND
U22 U23: library part TCK106AF,LF, "1.0 A Load Switch IC with Slew Rate Control Driver in Small Package", Manufacturer=Toshiba, Part number IPS=00000007823, Supplier Part Number 1=TCK106AFLFCT-ND
U26: library part AP2127K-ADJTRG1, "IC REG LDO ADJ 0.3A SOT23-5", Manufacturer="Diodes Incorporated", Part number IPS=N.A., Supplier Part Number 1=AP2127K-ADJTRG1DITR-ND
X1: library part XTAL_SMD2016_32MHz_8pF_Golledge, "XTAL SMD 2016, 32MHz, Cl=8pF, Tol: ±10ppm, Stab: ±15ppm", Manufacturer=Golledge, Manufacturer Part Number=MP06003, Part number IPS=N.A.
X2: library part XTAL_SMD3215_32.768kHz_9pF_NDK, "XTAL SMD 3215, 32.768kHz, 9pF, ±20ppm", Manufacturer=NDK, Manufacturer Part Number=NX3215SA-32.768K-STD-MUA-9, Part number IPS=N.A.
X20: library part XTAL_SMD3225_12MHz_18pF_TXC, "XTAL SMD 3225, 12MHz, Cl=18pF, Tol: ±30ppm, Stab: ±30ppm", Manufacturer="TXC Corporation", Manufacturer Part Number=7M-12.000MAAJ-T, Part number IPS=N.A., Supplier Part Number 1=887-1121-1-ND

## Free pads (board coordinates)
  round 3.2 hole 3.2 unplated: 1(13.97,7.62) 1(15.24,55.88) 1(66.04,12.7) 1(66.04,40.64) 1(90.17,55.88) 1(96.52,7.62) 1(128.27,46.355)
  round 0.35 on Mech16: 1(112.414,36.617) 1(112.414,37.117) 1(112.414,37.617) 1(112.414,38.117) 1(112.414,38.617) 1(114.164,34.867) 1(114.164,40.367) 1(114.414,34.367) 1(114.664,34.867) 1(114.664,40.367) 1(114.914,34.367) 1(115.164,34.867) 1(115.164,40.367) 1(115.664,34.867) 1(115.664,40.367) 1(116.164,34.867) 1(116.164,40.367) 1(116.664,34.867) 1(116.664,40.367) 1(117.164,34.867) 1(117.914,35.617) 1(117.914,36.117) 1(117.914,36.617) 1(117.914,37.117) 1(125.503,40.005) 1(128.753,37.255)

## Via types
v1: diameter 0.4, hole 0.2, Top Layer to Bottom Layer, tented both sides, 1691 vias
v2: diameter 0.35, hole 0.15, Top Layer to Mid-Layer 1, tented both sides, 184 vias
v3: diameter 0.61, hole 0.305, Top Layer to Bottom Layer, 24 vias
v4: diameter 0.61, hole 0.305, Top Layer to Bottom Layer, tented both sides, 16 vias
v5: diameter 0.5, hole 0.3, Top Layer to Bottom Layer, tented both sides, 12 vias
v6: diameter 0.35, hole 0.15, Top Layer to Mid-Layer 1, tented top, 8 vias
v7: diameter 0.4, hole 0.2, Top Layer to Mid-Layer 1, tented top, 2 vias
v8: diameter 0.35, hole 0.15, Top Layer to Bottom Layer, tented top, 1 vias

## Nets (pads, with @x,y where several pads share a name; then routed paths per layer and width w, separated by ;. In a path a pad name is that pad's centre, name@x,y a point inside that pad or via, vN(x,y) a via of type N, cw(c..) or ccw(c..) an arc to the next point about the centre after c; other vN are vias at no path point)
ANT1: A1.1 L9.2 | length 1.2
  Top Layer w0.3: L9.2@140.965,58.44 cw(c141.027,58.44) 140.983,58.483 A1.1@141.798,59.298
ANT2: A2.1 L11.2 | length 1.2
  Top Layer w0.203: A2.1@141.754,4.22 ccw(c141.798,4.264) A2.1@141.798,4.202
  Top Layer w0.3: L11.2@140.94,5.035 A2.1@141.754,4.22
ANT_SEL: R10.1 SB10.2 | length 26.3
  Top Layer w0.152: SB10.2@109.177,23.038 v1(109.763,23.038) ; v1(129.845,24.886) R10.1@129.845,29.383
  Bottom Layer w0.152: v1(109.763,23.038) 111.349,23.038 112.441,24.13 122.199,24.13 122.606,23.724 128.683,23.724 v1(129.845,24.886)
BOOT/RESET: R54.1 SB43.1 SW5.2 U7.16 | length 23.2
  Top Layer w0.152: SW5.2@73.917,6.502 SW5.2@80.667,6.502 ; v1(78.029,8.128) 78.241,8.128 SW5.2@79.913,6.456 ; v1(78.435,13.03) 79.18,13.03 R54.1@79.231,13.081 ; v1(80.645,16.459) 80.95,16.764 80.95,16.782 80.715,17.016 U7.16@80.715,19.11 U7.16@80.68,19.11
  Mid-Layer 2 w0.152: v1(78.435,13.03) 79.604,13.03 80.391,13.818 80.391,16.205 v1(80.645,16.459)
  Bottom Layer w0.152: v1(78.029,8.128) 78.029,12.624 v1(78.435,13.03)
BUCK_EN: SB29.2 U10.C2 U26.3 | length 39.4
  Top Layer w0.152: SB29.2@111.244,47.121 112.145,47.121 113.182,48.158 v1(116.865,48.158) ; U10.C2@113.497,59.9 113.753,59.9 113.954,59.699 v2(113.954,57.193) ; v2(124.282,57.193) 125.077,57.193 126.698,55.572 U26.3@126.698,55.292 126.698,55.037 124.282,52.621 124.282,49.796 124.76,49.319 v1(124.76,47.904)
  Mid-Layer 1 w0.152: v2(113.954,57.193) v2(124.282,57.193)
  Bottom Layer w0.152: v1(116.865,48.158) 117.119,47.904 v1(124.76,47.904)
CHL: R5.1 SB11.2 | length 44
  Top Layer w0.152: SB11.2@109.177,24.308 v1(109.765,24.308) ; v1(120.564,45.847) 121.05,45.847 121.699,45.198 121.699,43.952 122.282,43.369 R5.1@122.856,43.369
  Mid-Layer 2 w0.152: v1(109.55,44.602) 106.782,41.834 106.782,37.219 106.062,36.499 106.062,28.011 v1(109.765,24.308)
  Bottom Layer w0.152: v1(109.55,44.602) 109.019,45.133 109.019,46.626 109.847,47.454 120.604,47.454 120.915,47.143 120.915,46.198 v1(120.564,45.847)
CPS: R33.1 SB14.2 | length 48.1
  Top Layer w0.152: v1(110.998,23.665) 111.473,23.19 117.37,23.19 117.522,23.038 SB14.2@118.661,23.038 ; v1(120.384,46.923) 122.611,46.923 R33.1@122.856,46.678
  Mid-Layer 2 w0.152: v1(109.55,46.406) 109.982,45.974 109.982,44.417 107.086,41.522 107.086,37.042 106.373,36.329 106.373,28.318 110.998,23.693 v1(110.998,23.665)
  Bottom Layer w0.152: v1(109.55,46.406) 110.287,47.142 120.164,47.142 v1(120.384,46.923)
CRX: R8.1 SB12.2 | length 23.3
  Top Layer w0.152: SB12.2@109.177,25.578 109.598,25.156 v1(112.928,25.156) ; R8.1@126.526,29.383 126.526,25.233 v1(126.873,24.886)
  Bottom Layer w0.152: v1(112.928,25.156) 113.157,25.385 118.608,25.385 119.228,24.765 122.453,24.765 122.885,24.333 126.321,24.333 v1(126.873,24.886)
CSD: R9.1 SB15.2 | length 16
  Top Layer w0.152: v1(118.163,24.806) SB15.2@118.661,24.308 ; R9.1@128.185,29.383 128.185,24.799 v1@128.194,24.79
  Bottom Layer w0.152: v1(118.163,24.806) 118.515,24.454 122.333,24.454 122.758,24.028 127.337,24.028 v1(128.194,24.886)
CTX: R34.1 SB13.2 | length 49.5
  Top Layer w0.152: v1(110.203,23.665) 111.007,22.86 115.823,22.86 116.915,21.768 SB13.2@118.661,21.768 ; v1(119.782,46.38) 120.95,46.38 122.307,45.024 R34.1@122.856,45.024
  Mid-Layer 2 w0.152: v1(109.55,45.585) 106.477,42.512 106.477,37.371 105.751,36.646 105.751,27.558 109.645,23.665 v1(110.203,23.665)
  Bottom Layer w0.152: v1(109.55,45.585) 110.802,46.838 119.325,46.838 v1(119.782,46.38)
D*_N: D60.2 J3.2 R69.2 TP13.1 | length 39.8
  Top Layer w0.165: J3.2@89.086,5.985 89.086,8.495 ccw(c88.578,8.495) 88.938,8.855 D60.2@88.402,9.39 88.912,9.899 ccw(c88.114,10.697) 89.242,10.697 89.242,12.23 cw(c91.338,12.23) 91.338,14.326 ccw(c91.338,16.411) 92.813,14.936 94.183,16.307 ; 94.204,16.333 cw(c95.199,16.129) 94.995,17.124 ; 94.998,17.121 106.088,28.211 cw(c108.136,26.162) 108.136,29.06 113.295,29.06 ccw(c113.295,29.693) 113.928,29.693 113.928,30.023 ccw(c113.548,30.023) 113.817,30.291 R69.2@113.65,30.458
D*_P: D60.3 J3.3 R70.2 TP14.1 | length 39.9
  Top Layer w0.165: J3.3@89.734,5.983 89.734,8.495 cw(c90.242,8.495) 89.883,8.855 ; 89.883,8.854 D60.3@90.429,9.4 ; D60.3@90.44,9.39 89.931,9.899 cw(c90.729,10.697) 89.6,10.697 89.6,12.232 cw(c91.338,12.232) 91.338,13.97 ccw(c91.338,16.418) 93.069,14.687 93.522,15.139 ccw(c93.294,16.129) 94.284,15.901 ; 94.284,15.902 106.34,27.958 cw(c108.136,26.162) 108.136,28.702 113.295,28.702 ; 113.295,28.702 ccw(c113.295,29.693) 114.286,29.693 114.286,30.023 cw(c114.666,30.023) 114.397,30.291 R70.2@114.565,30.458
D_N: R69.1 U1.AD4 | length 3.4
  Top Layer w0.165: U1.AD4@112.914,34.367 112.982,34.299 112.982,34.061 ; 112.977,34.061 ccw(c113.89,34.061) 113.244,33.415 113.741,32.918 cw(c113.29,32.467) 113.928,32.467 113.928,32.004 cw(c113.282,32.004) 113.739,31.547 R69.1@113.65,31.458
D_P: R70.1 U1.AD6 | length 3.4
  Top Layer w0.165: U1.AD6@113.414,34.367 113.335,34.289 113.335,34.061 ccw(c113.89,34.061) 113.498,33.669 113.994,33.172 cw(c113.29,32.467) 114.286,32.467 114.286,32.004 ccw(c114.933,32.004) 114.476,31.547 R70.1@114.565,31.458
DEC1: C5.1 U1.C1 | length 2.3
  Top Layer w0.25: C5.1@109.824,40.455 110.851,40.455 111.439,39.867 U1.C1@111.914,39.867
DEC3: C11.1 U1.D23 | length 3
  Top Layer w0.152: U1.D23@117.914,39.617 117.919,39.617 118.244,39.942 118.514,39.942 120.114,41.542 C11.1@120.164,41.542
DEC4_6: C10.2 C15.2 C16.1 L3.1 U1.B5 U1.E24 | length 19.2
  Top Layer w0.15: U1.E24@118.414,39.367 118.414,39.423 119.657,40.667 v1(121.478,40.667)
  Top Layer w0.25: L3.1@111.864,44.992 111.864,42.867 112.139,42.592 v1(112.139,41.729) 113.064,40.805 113.064,40.544 113.164,40.444 U1.B5@113.164,40.367
  Bottom Layer w0.25: v1(112.139,41.729) 112.852,42.443 118.161,42.443 119.937,40.667 v1(121.478,40.667)
DFSD_N: R60.1 U2.80 | length 14.7
  Top Layer w0.165: R60.1@32.157,35.449 v1@33.138,36.43 ; v1@33.138,36.43 ccw(c33.017,36.551) v1(33.188,36.551) ; U2.80@36.179,29.403 38.065,29.403 ; 38.108,29.403 ccw(c38.108,30.023) v1@38.547,29.584
  Bottom Layer w0.165: v1(33.188,36.551) 34.193,36.551 cw(c34.193,34.011) 35.989,35.807 38.692,33.103 cw(c36.958,31.369) 39.411,31.369 cw(c37.181,31.369) 38.758,29.792 v1(38.547,29.582)
DFSD_P: R61.1 U2.81 | length 10.9
  Top Layer w0.165: R61.1@32.148,32.572 R61.1@32.157,32.581 ; R61.1@32.157,32.563 cw(c30.833,31.239) 32.705,31.239 v1(32.705,30.759) ; U2.81@36.179,28.9 38.09,28.9 ; 38.108,28.9 cw(c38.108,28.279) v1@38.547,28.718
  Bottom Layer w0.165: v1(32.705,30.759) cw(c32.705,28.736) 34.136,30.167 34.841,29.462 ccw(c36.637,31.258) 36.637,28.718 v1@38.547,28.718
  other v1: 38.547,28.721
DHSD_N: D61.2 J2.2 R60.2 TP10.1 U2.77 | length 38.5
  Top Layer w0.165: J2.2@4.619,32.398 6.34,32.398 ccw(c6.34,32.906) 6.699,32.546 D61.2@7.234,33.082 ; D61.2@7.244,33.105 cw(c7.211,33.105) D61.2@7.235,33.082 ; 13.153,32.259 ccw(c13.153,32.935) 13.631,32.457 14.84,33.666 ; 13.183,32.259 cw(c13.183,32.568) 12.964,32.349 12.88,32.433 ccw(c12.344,31.897) 12.344,32.655 ccw(c12.344,31.901) 11.811,32.434 11.727,32.35 cw(c11.506,32.571) 11.506,32.259 8.552,32.259 cw(c8.552,33.388) 7.754,32.59 7.244,33.099 D61.2@7.244,33.105 cw(c7.211,33.105) D61.2@7.234,33.082 ; 14.837,33.669 cw(c16.073,32.433) 16.073,34.181 ; 16.063,34.181 34.407,34.181 cw(c34.407,32.876) 35.33,33.799 37.203,31.926 ; U2.77@36.179,30.9 U2.77@36.774,30.9 ; 37.203,31.926 cw(c36.774,31.497) 36.774,30.891 ccw(c36.774,31.497) 37.203,31.926
DHSD_P: D61.3 J2.3 R61.2 TP9.1 U2.76 | length 37.9
  Top Layer w0.165: J2.3@4.619,31.75 6.34,31.75 cw(c6.34,31.242) 6.699,31.601 D61.3@7.244,31.055 7.244,31.062 7.754,31.571 ; 15.102,33.425 cw(c16.063,32.464) 16.063,33.823 34.407,33.823 ; 15.112,33.435 13.884,32.207 cw(c13.147,32.944) 13.147,31.901 11.405,31.901 ccw(c11.405,31.589) 11.184,31.81 11.1,31.726 cw(c10.566,32.259) 10.566,31.505 cw(c10.566,32.263) 10.031,31.727 9.947,31.811 ccw(c9.728,31.592) 9.728,31.901 8.551,31.901 ; 34.072,31.788 cw(c34.072,32.296) 34.072,32.804 ; 34.077,31.788 34.68,31.788 cw(c34.68,31.441) 34.925,31.686 ccw(c35.617,32.378) 35.617,31.4 U2.76@36.179,31.4 ; 34.082,32.804 34.382,32.804 ccw(c34.382,33.312) 34.382,33.82 ; 7.754,31.571 cw(c8.551,30.773) 8.551,31.901 ; 7.754,31.571 cw(c8.551,30.773) 8.551,31.901
EXT_GND_DETECT: P19.9 U2.67 | length 59.9
  Top Layer w0.152: v1(4.267,61.316) P19.9@5.836,61.316 ; v1(41.453,39.345) 42.088,38.71 42.088,37.897 42.088,37.236 42.088,37.084 42.088,34.344 41.754,34.011 U2.67@41.754,32.975
  Bottom Layer w0.152: v1(4.267,61.316) 4.427,61.316 15.603,50.14 39.597,50.14 40.513,49.224 40.513,40.284 v1(41.453,39.345)
EXT_RESET: P19.10 U2.68 | length 60.5
  Top Layer w0.152: P19.10@1.936,61.316 v1(3.505,61.316) ; U2.68@41.25,32.98 U2.68@41.254,32.975 41.254,33.833 41.254,33.942 41.783,34.47 41.783,38.176 v1(41.377,38.583)
  Bottom Layer w0.152: v1(3.505,61.316) 4.14,60.681 4.631,60.681 15.477,49.835 39.471,49.835 40.208,49.097 40.208,39.413 41.039,38.583 v1(41.377,38.583)
EXT_SWDCLK: P19.4 U2.70 | length 57.5
  Top Layer w0.152: P19.4@1.936,57.506 v1(3.505,57.506) ; U2.70@40.254,32.975 40.254,33.778 41.199,34.723 v1(41.199,35.687)
  Bottom Layer w0.152: v1(3.505,57.506) 6.944,57.506 15.224,49.225 37.667,49.225 38.176,48.716 38.176,40.583 41.046,37.713 41.046,37.16 41.453,36.754 41.453,35.941 v1(41.199,35.687)
EXT_SWDIO: P19.2 U2.71 | length 56.5
  Top Layer w0.152: P19.2@1.936,56.236 v1(3.505,56.236) ; U2.71@39.754,32.975 39.754,33.709 40.64,34.595 40.64,36.246 v1(40.919,36.525)
  Bottom Layer w0.152: v1(3.505,56.236) 7.783,56.236 15.098,48.92 37.541,48.92 37.871,48.59 37.871,40.457 40.742,37.587 40.742,36.703 v1(40.919,36.525)
EXT_SWO: P19.6 U2.18 | length 77.7
  Top Layer w0.152: P19.6@1.936,58.776 v1(3.505,58.776) ; v1(41.173,31.648) 41.351,31.826 42.189,31.826 43.84,30.175 43.84,28.829 46.888,25.781 46.888,19.66 46.254,19.025 U2.18@46.254,17.825
  Bottom Layer w0.152: v1(3.505,58.776) 6.108,58.776 6.407,58.477 ; 6.405,58.475 15.351,49.53 39.345,49.53 39.903,48.971 39.903,39.287 41.351,37.839 41.351,37.286 41.758,36.88 41.758,32.233 v1(41.173,31.648)
EXT_VTG: P19.1 Q3.4 R24.1 SB47.2 | length 9.1
  Top Layer w0.203: R24.1@8.661,58.945 8.693,58.914 Q3.4@9.712,58.914
  Top Layer w0.254: P19.1@5.836,56.49 7.264,56.49 7.772,56.998 7.772,58.056 R24.1@8.661,58.945 8.298,59.309 SB47.2@8.298,62.408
